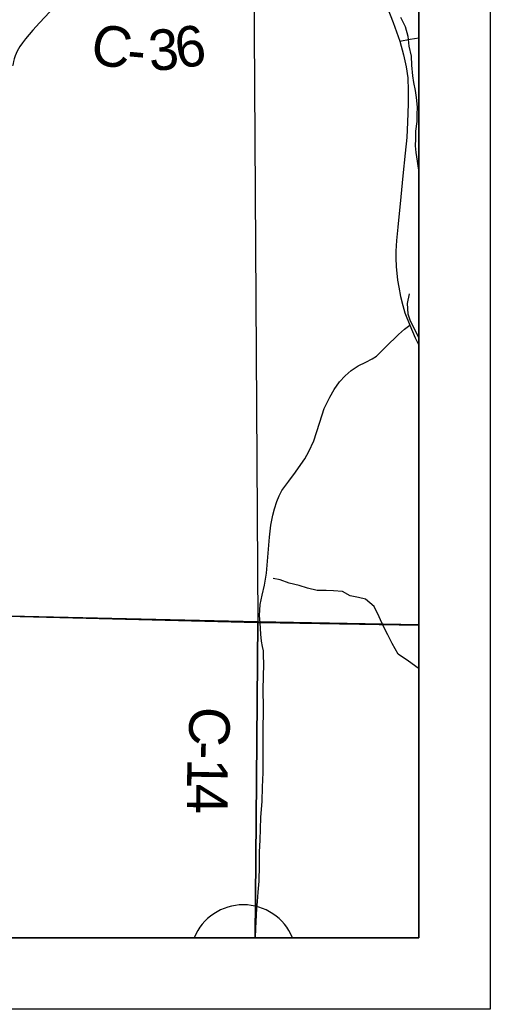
# Model space of a CAD drawing. Extents: x 0 to 34, y 0 to 22.
# Drawn here: x 29.759 to 30.417, y 14 to 15.384 of the extents above; entities that cross this region are included whole.
import ezdxf

# ---------------------------------------------------------------- set-up
doc = ezdxf.new("R2010")
doc.units = 0
for name, color, linetype in [('GM_X_Corporation', 7, 'Continuous'), ('GM_X_Corporation_Text', 7, 'Continuous'), ('GM_X_County_Road', 7, 'Continuous'), ('GM_X_County_Road_Text', 7, 'Continuous'), ('GM_X_Minor_River', 7, 'Continuous'), ('GM_X_State_Route', 7, 'Continuous'), ('GM_X_Township_Road', 7, 'Continuous'), ('SH_Data', 7, 'Continuous')]:
    doc.layers.add(name, color=color, linetype=linetype)

msp = doc.modelspace()

# ---------------------------------------------------------------- linework, layer by layer
at = {"layer": 'GM_X_Corporation'}
for points in [[(23.5167, 14.1), (30.3167, 14.1), (30.3167, 18.565), (30.101, 18.5701), (29.6772, 18.5786), (29.6561, 18.5791), (29.0074, 18.5935), (28.7772, 18.6028), (28.3421, 18.6121), (27.3971, 18.6436), (27.1064, 18.6537), (27.1039, 18.5696), (27.0944, 18.0731), (27.0775, 16.888), (27.0694, 16.6556), (27.0676, 16.5549), (27.052, 15.403), (27.043, 14.755), (27.046, 14.6155), (27.01, 14.6164), (26.6535, 14.621)], [(27.0676, 16.5549), (27.052, 15.403), (27.043, 14.755), (27.046, 14.6155), (27.2076, 14.6118), (27.2151, 14.6117), (27.2601, 14.6106), (27.262, 14.6106), (27.3217, 14.6092), (27.3244, 14.6092), (28.7538, 14.5726), (28.7592, 14.5724), (28.9743, 14.568), (28.9779, 14.5679), (28.9904, 14.5676), (29.257, 14.5621), (29.2606, 14.562), (30.0913, 14.5411), (30.0947, 14.5411), (30.3167, 14.5373), (30.3167, 18.565)], [(26.0358, 14.1), (30.3167, 14.1), (30.3167, 14.5373), (30.0947, 14.5411), (30.0913, 14.5411), (29.2606, 14.562), (29.257, 14.5621), (28.9904, 14.5676), (28.9779, 14.5679), (28.9743, 14.568), (28.7592, 14.5724), (28.7538, 14.5726), (27.3244, 14.6092), (27.3217, 14.6092), (27.262, 14.6106), (27.2601, 14.6106), (27.2151, 14.6117), (27.2076, 14.6118), (27.046, 14.6155), (27.01, 14.6164), (26.6535, 14.621)]]:
    msp.add_lwpolyline(points, dxfattribs=at)
for points in [[(30.0852, 15.5935), (30.0916, 14.542), (29.1115, 14.5644), (29.0455, 14.5648), (29.0554, 15.5858)], [(30.3167, 14.5377), (30.3167, 15.5879), (30.0852, 15.5935), (30.0916, 14.542)], [(29.1022, 14.1), (30.0878, 14.1), (30.0916, 14.542), (29.1115, 14.5644)], [(30.0878, 14.1), (30.3167, 14.1), (30.3167, 14.5377), (30.0916, 14.542)]]:
    msp.add_lwpolyline(points, close=True, dxfattribs=at)
at = {"layer": 'GM_X_Corporation_Text'}
msp.add_line((30.0025, 14.1), (30.1401, 14.1), dxfattribs=at)
msp.add_arc((30.0713, 14.0717), 0.0744, 22.3427, 157.6573, dxfattribs=at)
at = {"layer": 'GM_X_County_Road'}
for points in [[(29.8077, 15.4032), (29.7862, 15.3803), (29.7766, 15.3701), (29.7665, 15.3579), (29.7621, 15.3522), (29.7585, 15.3469), (29.755, 15.3404), (29.7523, 15.3341), (29.7506, 15.3298), (29.7497, 15.3262), (29.749, 15.3205), (29.6916, 15.322), (29.6482, 15.3218), (29.6144, 15.3211), (29.5752, 15.3187), (29.5633, 15.3221), (29.5567, 15.3252), (29.5516, 15.3291), (29.5282, 15.3538), (29.4987, 15.3865)], [(30.0953, 14.5326), (30.0949, 14.5405), (30.0941, 14.5509), (30.0945, 14.5585), (30.095, 14.5665), (30.0976, 14.5793), (30.101, 14.5931), (30.1038, 14.6099), (30.108, 14.6603), (30.1099, 14.6773), (30.1126, 14.6915), (30.1149, 14.7001), (30.1183, 14.7105), (30.1215, 14.7182), (30.1253, 14.7257), (30.1348, 14.7388), (30.1443, 14.7515), (30.1518, 14.762), (30.1573, 14.7703), (30.1627, 14.7804), (30.1698, 14.7951), (30.1738, 14.8069), (30.1781, 14.8213), (30.1845, 14.8403), (30.1881, 14.8482), (30.1921, 14.8564), (30.1982, 14.8669), (30.2058, 14.8777), (30.2139, 14.8863), (30.2221, 14.8937), (30.2319, 14.9001), (30.2427, 14.9054), (30.2513, 14.9098), (30.2574, 14.9139), (30.2619, 14.9178), (30.2705, 14.9267), (30.2883, 14.944), (30.2966, 14.9517), (30.304, 14.9569)], [(30.0883, 14.1), (30.0887, 14.1136), (30.0903, 14.1408), (30.091, 14.1506), (30.0921, 14.1639), (30.0933, 14.1791), (30.094, 14.2011), (30.094, 14.2201), (30.0948, 14.2365), (30.0959, 14.2683), (30.0975, 14.2909), (30.098, 14.3106), (30.0988, 14.3313), (30.0989, 14.3599), (30.0991, 14.3883), (30.0993, 14.4211), (30.0988, 14.448), (30.0999, 14.4827), (30.0994, 14.4955), (30.0993, 14.5014), (30.0981, 14.5076), (30.0969, 14.5148), (30.0957, 14.5246), (30.0953, 14.5326)]]:
    msp.add_lwpolyline(points, dxfattribs=at)
at = {"layer": 'GM_X_Minor_River'}
for points in [[(30.291, 15.3882), (30.2975, 15.375), (30.3013, 15.3617), (30.3029, 15.3477), (30.306, 15.3337), (30.3064, 15.3208), (30.3079, 15.306), (30.3095, 15.2966), (30.3118, 15.2856), (30.3133, 15.2757), (30.3145, 15.2621), (30.3141, 15.2518), (30.3138, 15.242), (30.3123, 15.2287), (30.312, 15.2177), (30.3116, 15.2082), (30.3128, 15.1988), (30.3143, 15.1866), (30.3159, 15.1768), (30.3167, 15.1728)], [(30.3035, 15.0009), (30.3005, 14.9876), (30.3013, 14.9732), (30.3048, 14.963), (30.3167, 14.9393)], [(30.3167, 14.4768), (30.3157, 14.4774), (30.3024, 14.4868), (30.288, 14.497), (30.2796, 14.5118), (30.2735, 14.5239), (30.2674, 14.5356), (30.2613, 14.5492), (30.2541, 14.5636), (30.2423, 14.5738), (30.2325, 14.5761), (30.2207, 14.5783), (30.2101, 14.5843), (30.1972, 14.5854), (30.1874, 14.5861), (30.1745, 14.5861), (30.1609, 14.5891), (30.1495, 14.5928), (30.1355, 14.5962), (30.1226, 14.6007), (30.1131, 14.6026)]]:
    msp.add_lwpolyline(points, dxfattribs=at)
at = {"layer": 'GM_X_State_Route'}
msp.add_lwpolyline([(30.2714, 15.4045), (30.2807, 15.3807), (30.2901, 15.3544), (30.2953, 15.3356), (30.2989, 15.3188), (30.3012, 15.3031), (30.3021, 15.2854), (30.302, 15.267), (30.301, 15.241), (30.2998, 15.2196), (30.2976, 15.1976), (30.2945, 15.1662), (30.2917, 15.1366), (30.2874, 15.0941), (30.2856, 15.0755), (30.2847, 15.0605), (30.2848, 15.0509), (30.2851, 15.039), (30.2871, 15.0199), (30.2889, 15.0103), (30.2911, 14.9973), (30.2943, 14.9846), (30.2974, 14.9745), (30.304, 14.9569), (30.3118, 14.9395), (30.3167, 14.9291)], dxfattribs=at)
at = {"layer": 'GM_X_Township_Road'}
msp.add_lwpolyline([(30.2901, 15.3544), (30.3049, 15.3573), (30.3167, 15.3593)], dxfattribs=at)
at = {"layer": 'SH_Data'}
for points in [[(23.4167, 21), (30.4167, 21), (30.4167, 14), (23.4167, 14)], [(23.5167, 20.9), (30.3167, 20.9), (30.3167, 14.1), (23.5167, 14.1)]]:
    msp.add_lwpolyline(points, close=True, dxfattribs=at)

# ---------------------------------------------------------------- texts
at = {"layer": 'GM_X_County_Road_Text'}
for s, rotation, p in [('C', 348.8409, (29.8549, 15.3248)), ('3', 4.4346, (29.9407, 15.3127)), ('6', 8.6819, (29.9802, 15.3159)), ('-', 354.9122, (29.9072, 15.3148)), ('C', 265.4717, (29.9978, 14.425)), ('-', 267.9834, (29.9939, 14.3757)), ('1', 269.0142, (29.9931, 14.3513)), ('4', 269.8612, (29.9925, 14.3154))]:
    msp.add_text(s, height=0.0568, rotation=rotation, dxfattribs=at).set_placement(p)

doc.saveas('drawing.dxf')
